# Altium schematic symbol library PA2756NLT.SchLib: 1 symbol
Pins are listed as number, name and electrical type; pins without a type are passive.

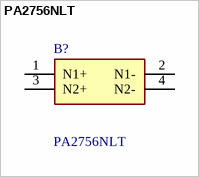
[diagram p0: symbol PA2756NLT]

## PA2756NLT
designator B?
Common Mode Chokes / Filters 484 UH 8A; Manufacturer_Name: PULSE; Geometry.Height: 9.91mm
footprint PA2756NLT
pins: 1 N1+, 2 N1-, 3 N2+, 4 N2-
